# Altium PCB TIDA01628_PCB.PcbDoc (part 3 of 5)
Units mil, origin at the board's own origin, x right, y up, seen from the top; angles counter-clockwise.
Board outline 14212.6 x 5944.88 mil, 4 copper layers (Top Layer, GND, 5V, Bottom Layer), stack 60.8 mil thick; 304 components, 201 nets, 839 pads, 2143 vias.
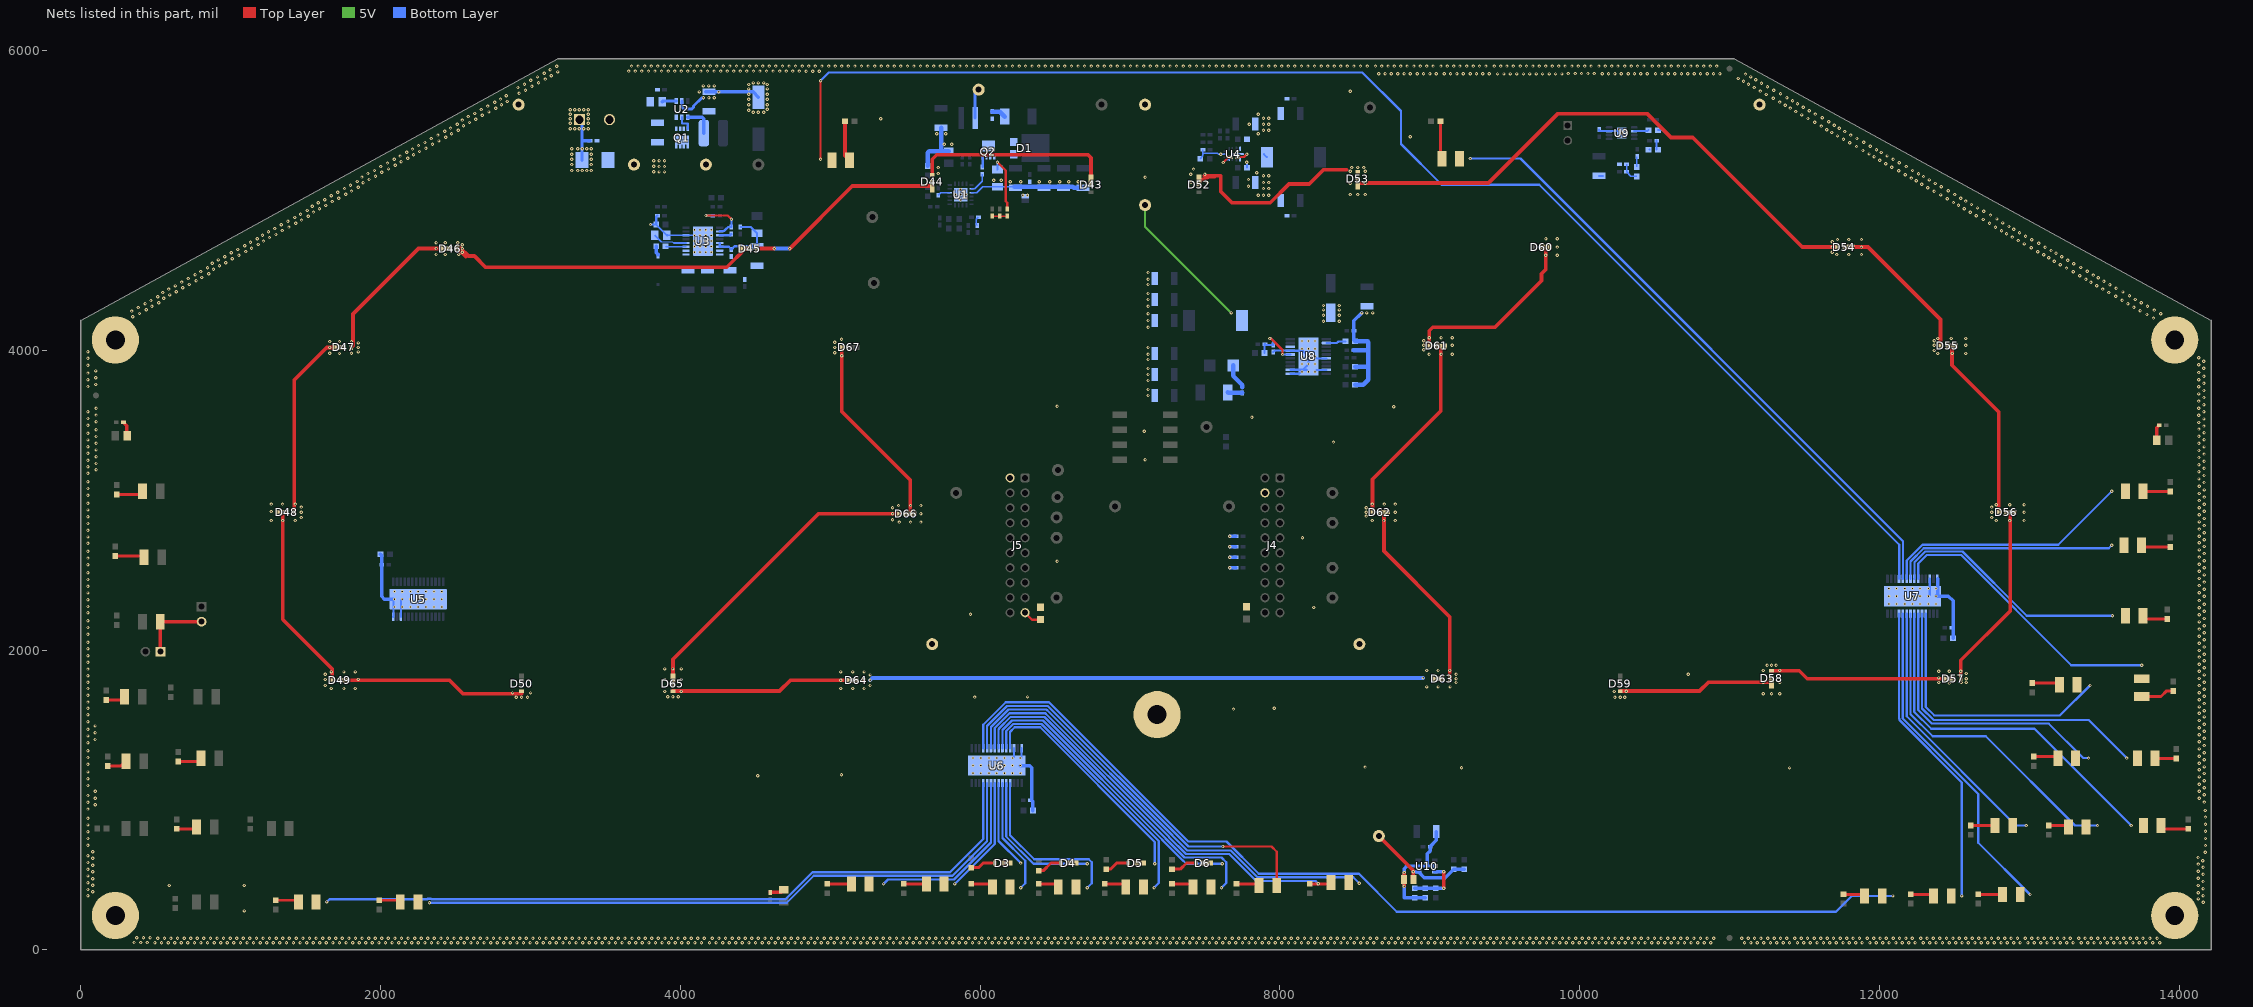
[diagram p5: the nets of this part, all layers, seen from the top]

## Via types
v1: diameter 22, hole 10, Top Layer to Bottom Layer, 1391 vias
v2: diameter 22, hole 10, Top Layer to Bottom Layer, tented both sides, 644 vias
v3: diameter 19.68, hole 7.87, Top Layer to Bottom Layer, tented both sides, 56 vias
v4: diameter 19.68, hole 7.87, Top Layer to Bottom Layer, 47 vias
v5: diameter 19.68, hole 7.87, Top Layer to Bottom Layer, tented top, 5 vias

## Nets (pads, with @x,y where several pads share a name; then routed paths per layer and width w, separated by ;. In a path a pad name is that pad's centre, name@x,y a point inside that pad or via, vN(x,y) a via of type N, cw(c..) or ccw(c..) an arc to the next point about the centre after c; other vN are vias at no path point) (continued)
GND: C2.2 C3.2 C4.2 C5.2 C6.2 C7.2 C8.2 C9.2 C10.2 C12.2 C16.2 C17.1 C20.2 C21.2 C23.2 C24.2 C25.2 C26.2 C29.2 C30.2 C31.2 C32.2 C33.1 C34.2 C35.2 C36.2 C37.2 C38.2 C40.2 C41.2 C42.2 C43.2 C44.2 C45.2 C46.2 C47.2 C48.2 C49.2 C50.2 C51.2 C52.2 C53.2 C55.2 C56.2 C57.2 C58.2 C59.2 C60.2 C62.2 C63.2 C64.2 C65.2 C66.2 C68.2 C69.2 C71.2 C72.2 C73.2 C74.2 C75.2 C76.2 D2.1 D68.2 D69.2 H1.1 H2.1 H3.1 H4.1 H5.1 J1.1 J4.4 J5.2 NTG1.2 Q3.1 R4.1 R17.1 R19.1 R23.1 R66.1 R68.1 R69.2 R78.1 R79.1 R80.1 R81.1 R82.1 TP7.1 TP8.1 TP9.1 TP10.1 TP11.1 U1.10 U1.17@5870,5040 U2.2 U3.6 U3.10 U3.15 U3.16 U3.17@4150,4730 U4.1 U4.6 U4.11 U5.26 U5.28 U5.29@2250,2340 U6.26 U6.28 U6.29@6110,1230 U7.26 U7.28 U7.29@12220,2360 U8.6 U8.9 U8.11 U8.12 U8.17 U8.21@8190,3960 U9.7 U9.9 U10.2 | length 8014
  Top Layer w15: v2(4170,4900) 4315,4900 v2(4340,4875)
  Top Layer w23: C42.2@283.62,3520 305.28,3498.35 305.28,3434.72 C43.2@310,3430 ; C44.2@4600,383.62 4673.62,383.62 C45.2@4690,400 ; v2(8828,424) 8828.5,424.5 v2(8828.5,516) ; C47.2@13850,3400 13850,3483.62 C46.2@13866.38,3500
  Bottom Layer w9: C40.2@7468.5,5280 C40.2@7486.38,5297.87 ; 7486.38,5310 7487.45,5311.07 ; v2@7603.93,5311.07 v2(7605,5310) U4.6@7634.88,5310
  Bottom Layer w10: U1.10@5941.85,5052.8 5977.8,5052.8 6017.91,5092.91 R4.1@6115.12,5092.91 6227.24,5092.91 C6.2@6235.12,5085.04 ; C40.2@7486.38,5297.87 7486.38,5310 R23.1@7486.38,5340 ; 7487.45,5311.07 7491.38,5315 7585,5315 7590,5310 v2(7605,5310)
  Bottom Layer w13: v2(3800,4840) C34.2@3838.5,4840 3840,4840 C33.1@3910,4770 ; C33.1@3911.61,4768.39 U3.6@4037.79,4768.39 4092.91,4768.39 v3(4093.9,4767.4) ; C30.2@7781.5,5220 v2@7781.5,5258.5 ; R66.1@7965.21,3998.39 U8.17@8069.92,3998.39 ; v3(8233.31,3857.64) 8246.1,3870.43 U8.9@8310.08,3870.43 ; v4(8233.31,3960) 8246.1,3947.2 U8.6@8310.08,3947.2 ; C68.2@10130,5165.04 C68.2@10155.04,5165.04 ; C69.2@10130,5473.62 10130,5465.15 10193.98,5465.15 U9.7@10196.34,5462.8 10251.46,5462.8 v4(10262.28,5473.62) ; C72.2@10466,5339.62 C72.2@10466.38,5340 ; C73.2@10521.5,5470 10550,5470 10567,5453
  Bottom Layer w15: U5.28@2083.66,2223.86 2085.02,2225.22 2085.02,2340 v3(2092.52,2340) ; U5.26@2134.84,2223.86 2134.84,2331.14 v3(2143.7,2340) ; C34.2@3838.5,4840 3838.5,4892.13 R17.1@3846.38,4900 ; C33.1@3910,4770 C33.1@3911.61,4768.39 ; v2(4170,4900) R19.1@4216.38,4900 ; U3.10@4262.2,4793.98 4264.55,4796.32 4291.04,4796.32 4301.2,4806.48 4301.2,4806.7 4318.12,4823.62 C41.2@4340,4823.62 v2(4340,4875) ; v3(6216.3,1281.18) 6225.16,1290.04 U6.26@6225.16,1346.14 ; v3(6267.48,1281.18) 6274.98,1281.18 6274.98,1344.78 U6.28@6276.34,1346.14 ; R66.1@7956,3989.18 R66.1@7965.21,3998.39 ; U8.11@8069.92,3844.84 8127.2,3844.84 U8.21@8152.8,3870.43 ; U8.12@8069.92,3870.43 U8.21@8152.8,3870.43 ; U8.17@8069.92,3998.39 8151.61,3998.39 v4(8190,3960) v4(8190,3908.82) 8190,3907.64 U8.21@8152.8,3870.43 ; v3(8190,3857.64) 8177.2,3870.43 U8.21@8152.8,3870.43 ; v3(12326.3,2360) 12335.16,2368.86 U7.26@12335.16,2476.14
  Bottom Layer w20: U2.2@4010,5664.13 4010,5621.83 4019.83,5612 4076.9,5612 4087.13,5622.23 4087.13,5630.62 4141.5,5685 v2(4153.69,5685)
  Bottom Layer w23: C49.2@1998.5,2640 2006.38,2632.13 C48.2@2006.38,2570 2006.38,2358.62 2025,2340 U5.29@2085.02,2340 ; J1.1@3326.55,5540 3342.99,5523.55 3342.99,5396.78 ; D2.1@3342.99,5270 3342.99,5396.78 ; C10.2@3396.38,5400 3346.21,5400 3342.99,5396.78 ; C2.2@4169.96,5724.96 C2.2@4190,5724.96 4484.8,5724.96 C8.2@4520,5689.76 ; v3(6267.48,1230) 6330,1230 6343.62,1216.38 6343.62,1000 6351.5,992.13 C53.2@6351.5,930 ; v2(7665,2550) R82.1@7706.38,2550 ; v2(7665,2620) R81.1@7706.38,2620 ; v2(7665,2690) R80.1@7706.38,2690 ; v2(7665,2760) R79.1@7706.38,2760 ; C66.2@8501.18,4060 8493.62,4067.56 C62.2@8493.62,4130 8493.62,4198.62 v2(8545,4250) ; R78.1@8968.7,348.5 C74.2@8898.7,348.5 8828.5,348.5 v2(8828.5,516) 8828.5,542.5 8846,560 U10.2@9032.83,560 ; 8984,562 8984,642 9002.32,660.32 C76.2@9002.32,690 9043.66,731.34 C75.2@9043.66,790 ; U7.28@12388.98,2476.14 12388.98,2371.5 v3(12377.48,2360) 12460,2360 12491.5,2328.5 C51.2@12491.5,2080
  Bottom Layer w30: C17.1@5650,5231.5 5650,5320 5660,5330 5740,5330 ; C12.2@5740,5485.04 5740,5330 ; C16.2@5790,5330 5740,5330 ; C6.2@6227.24,5092.91 6617.24,5092.91 6625.12,5085.04 C5.2@6683.78,5085.04 ; R68.1@8493.62,4000 8585,4000 8590,3995 ; C66.2@8501.18,4060 8585,4060 8590,4055 8590,3995 ; R69.2@8501.5,3770 8555,3770 8590,3805 8590,3890 ; C65.2@8501.5,3890 8590,3890 ; 8590,3890 8590,3995
  other v1: 494.04,47.45 537.89,47.45 581.74,47.45 625.59,47.45 669.44,47.45 713.29,47.45 757.14,47.45 800.99,47.45 844.84,47.45 888.69,47.45 932.54,47.45 976.39,47.45 1020.24,47.45 1064.09,47.45 1107.94,47.45 1151.79,47.45 1195.64,47.45 1239.49,47.45 1283.34,47.45 1327.19,47.45 1371.04,47.45 1418.04,47.45 1461.89,47.45 1505.74,47.45 1549.59,47.45 1593.44,47.45 1637.29,47.45 1681.14,47.45 1724.99,47.45 1768.84,47.45 1812.69,47.45 1856.54,47.45 1900.39,47.45 1944.24,47.45 1988.09,47.45 2031.94,47.45 2075.79,47.45 2119.64,47.45 2163.49,47.45 2207.34,47.45 2251.19,47.45 2295.04,47.45 2338.89,47.45 2382.74,47.45 2426.59,47.45 2470.44,47.45 2514.29,47.45 2558.14,47.45 2601.99,47.45 2645.84,47.45 2689.69,47.45 2733.54,47.45 2777.39,47.45 2821.24,47.45 2865.09,47.45 2908.94,47.45 2952.79,47.45 2996.64,47.45 3040.49,47.45 3084.34,47.45 3128.19,47.45 3172.04,47.45 3215.89,47.45 3259.74,47.45 3303.59,47.45 3347.44,47.45 3391.29,47.45 3435.14,47.45 3478.99,47.45 3522.84,47.45 3566.69,47.45 3610.54,47.45 3658.04,47.45 3701.89,47.45 3745.74,47.45 3789.59,47.45 3833.44,47.45 3877.29,47.45 3921.14,47.45 3964.99,47.45 4008.84,47.45 4052.69,47.45 4096.54,47.45 4140.39,47.45 4194.04,47.45 4237.89,47.45 4281.74,47.45 4325.59,47.45 4369.44,47.45 4413.29,47.45 4457.14,47.45 4500.99,47.45 4544.84,47.45 4588.69,47.45 4632.54,47.45 4676.39,47.45 4720.24,47.45 4764.09,47.45 4807.94,47.45 4851.79,47.45 4895.64,47.45 4939.49,47.45 4983.34,47.45 5027.19,47.45 5071.04,47.45 5114.89,47.45 5158.74,47.45 5202.59,47.45 5246.44,47.45 5290.29,47.45 5334.14,47.45 5377.99,47.45 5421.84,47.45 5465.69,47.45 5509.54,47.45 5553.39,47.45 5597.24,47.45 5641.09,47.45 5684.94,47.45 5728.79,47.45 5772.64,47.45 5816.49,47.45 5860.34,47.45 5904.19,47.45 5948.04,47.45 5991.89,47.45 6035.74,47.45 6079.59,47.45 6123.44,47.45 6167.29,47.45 6211.14,47.45 6254.99,47.45 6298.84,47.45 6342.69,47.45 6386.54,47.45 6434.04,47.45 6477.89,47.45 6521.74,47.45 6565.59,47.45 6609.44,47.45 6653.29,47.45 6697.14,47.45 6740.99,47.45 6784.84,47.45 6828.69,47.45 6872.54,47.45 6916.39,47.45 6960.24,47.45 7004.09,47.45 7047.94,47.45 7091.79,47.45 7135.64,47.45 7179.49,47.45 7223.34,47.45 7267.19,47.45 7311.04,47.45 7354.89,47.45 7398.74,47.45 7442.59,47.45 7486.44,47.45 7530.29,47.45 7574.14,47.45 7617.99,47.45 7661.84,47.45 7705.69,47.45 7749.54,47.45 7793.39,47.45 7837.24,47.45 7881.09,47.45 7924.94,47.45 7968.79,47.45 8012.64,47.45 8056.49,47.45 8100.34,47.45 8144.19,47.45 8188.04,47.45 8231.89,47.45 8275.74,47.45 8319.59,47.45 8363.44,47.45 8407.29,47.45 8451.14,47.45 8494.99,47.45 8538.84,47.45 8582.69,47.45 8626.54,47.45 8682.04,47.45 8725.89,47.45 8769.74,47.45 8813.59,47.45 8857.44,47.45 8901.29,47.45 8945.14,47.45 8988.99,47.45 9032.84,47.45 9076.69,47.45 9120.54,47.45 9164.39,47.45 9208.24,47.45 9252.09,47.45 9295.94,47.45 9339.79,47.45 9383.64,47.45 9427.49,47.45 9471.34,47.45 9515.19,47.45 9559.04,47.45 9602.89,47.45 9646.74,47.45 9690.59,47.45 9734.44,47.45 9778.29,47.45 9822.14,47.45 9865.99,47.45 9909.84,47.45 9953.69,47.45 9997.54,47.45 10041.39,47.45 10085.24,47.45 10129.09,47.45 10172.94,47.45 10216.79,47.45 10260.64,47.45 10304.49,47.45 10348.34,47.45 10392.19,47.45 10436.04,47.45 10479.89,47.45 10523.74,47.45 10567.59,47.45 10611.44,47.45 10655.29,47.45 10699.14,47.45 10742.99,47.45 10786.84,47.45 10830.69,47.45 10874.54,47.45 13823,47 13870,47 11100,47.92 11142.44,47.92 11184.87,47.92 11227.31,47.92 11273,47.92 11315.44,47.92 11357.87,47.92 11400.31,47.92 11453,47.92 11495.44,47.92 11537.87,47.92 11584,47.92 11626.44,47.92 11668.87,47.92 11711.31,47.92 11757,47.92 11799.44,47.92 11841.87,47.92 11884.31,47.92 11937,47.92 11979.44,47.92 12021.87,47.92 12064.31,47.92 12110,47.92 12152.44,47.92 12194.87,47.92 12237.31,47.92 12293,47.92 12335.44,47.92 12377.87,47.92 12420.31,47.92 12466,47.92 12508.44,47.92 12550.87,47.92 12593.31,47.92 12637.44,47.92 12679.87,47.92 12722.31,47.92 12765.5,47.92 12811.19,47.92 12853.63,47.92 12896.06,47.92 12938.5,47.92 12991.19,47.92 13033.63,47.92 13076.06,47.92 13118.5,47.92 13164.19,47.92 13206.63,47.92 13249.06,47.92 13291.5,47.92 13347.19,47.92 13389.63,47.92 13432.06,47.92 13474.5,47.92 13520.19,47.92 13562.63,47.92 13605.06,47.92 13647.5,47.92 13691.63,47.92 13734.06,47.92 13776.5,47.92 354.22,49.52 398.07,49.52 441.92,49.52 13805,78 13852,78 513.13,78.92 556.98,78.92 600.83,78.92 644.68,78.92 688.53,78.92 732.38,78.92 776.23,78.92 820.08,78.92 863.93,78.92 907.78,78.92 951.63,78.92 995.48,78.92 1039.33,78.92 1083.18,78.92 1127.03,78.92 1170.88,78.92 1214.73,78.92 1258.58,78.92 1302.43,78.92 1346.28,78.92 1390.13,78.92 1437.13,78.92 1480.98,78.92 1524.83,78.92 1568.68,78.92 1612.53,78.92 1656.38,78.92 1700.23,78.92 1744.08,78.92 1787.93,78.92 1831.78,78.92 1875.63,78.92 1919.48,78.92 1963.33,78.92 2007.18,78.92 2051.03,78.92 2094.88,78.92 2138.73,78.92 2182.58,78.92 2226.43,78.92 2270.28,78.92 2314.13,78.92 2357.98,78.92 2401.83,78.92 2445.68,78.92 2489.53,78.92 2533.38,78.92 2577.23,78.92 2621.08,78.92 2664.93,78.92 2708.78,78.92 2752.63,78.92 2796.48,78.92 2840.33,78.92 2884.18,78.92 2928.03,78.92 2971.88,78.92 3015.73,78.92 3059.58,78.92 3103.43,78.92 3147.28,78.92 3191.13,78.92 3234.98,78.92 3278.83,78.92 3322.68,78.92 3366.53,78.92 3410.38,78.92 3454.23,78.92 3498.08,78.92 3541.93,78.92 3585.78,78.92 3629.63,78.92 3677.13,78.92 3720.98,78.92 3764.83,78.92 3808.68,78.92 3852.53,78.92 3896.38,78.92 3940.23,78.92 3984.08,78.92 4027.93,78.92 4071.78,78.92 4115.63,78.92 4159.48,78.92 4213.13,78.92 4256.98,78.92 4300.83,78.92 4344.68,78.92 4388.53,78.92 4432.38,78.92 4476.23,78.92 4520.08,78.92 4563.93,78.92 4607.78,78.92 4651.63,78.92 4695.48,78.92 4739.33,78.92 4783.18,78.92 4827.03,78.92 4870.88,78.92 4914.73,78.92 4958.58,78.92 5002.43,78.92 5046.28,78.92 5090.13,78.92 5133.98,78.92 5177.83,78.92 5221.68,78.92 5265.53,78.92 5309.38,78.92 5353.23,78.92 5397.08,78.92 5440.93,78.92 5484.78,78.92 5528.63,78.92 5572.48,78.92 5616.33,78.92 5660.18,78.92 5704.03,78.92 5747.88,78.92 5791.73,78.92 5835.58,78.92 5879.43,78.92 5923.28,78.92 5967.13,78.92 6010.98,78.92 6054.83,78.92 6098.68,78.92 6142.53,78.92 6186.38,78.92 6230.23,78.92 6274.08,78.92 6317.93,78.92 6361.78,78.92 6405.63,78.92 6453.13,78.92 6496.98,78.92 6540.83,78.92 6584.68,78.92 6628.53,78.92 6672.38,78.92 6716.23,78.92 6760.08,78.92 6803.93,78.92 6847.78,78.92 6891.63,78.92 6935.48,78.92 6979.33,78.92 7023.18,78.92 7067.03,78.92 7110.88,78.92 7154.73,78.92 7198.58,78.92 7242.43,78.92 7286.28,78.92 7330.13,78.92 7373.98,78.92 7417.83,78.92 7461.68,78.92 7505.53,78.92 7549.38,78.92 7593.23,78.92 7637.08,78.92 7680.93,78.92 7724.78,78.92 7768.63,78.92 7812.48,78.92 7856.33,78.92 7900.18,78.92 7944.03,78.92 7987.88,78.92 8031.73,78.92 8075.58,78.92 8119.43,78.92 8163.28,78.92 8207.13,78.92 8250.98,78.92 8294.83,78.92 8338.68,78.92 8382.53,78.92 8426.38,78.92 8470.23,78.92 8514.08,78.92 8557.93,78.92 8601.78,78.92 8645.63,78.92 8701.13,78.92 8744.98,78.92 8788.83,78.92 8832.68,78.92 8876.53,78.92 8920.38,78.92 8964.23,78.92 9008.08,78.92 9051.93,78.92 9095.78,78.92 9139.63,78.92 9183.48,78.92 9227.33,78.92 9271.18,78.92 9315.03,78.92 9358.88,78.92 9402.73,78.92 9446.58,78.92 9490.43,78.92 9534.28,78.92 9578.13,78.92 9621.98,78.92 9665.83,78.92 9709.68,78.92 9753.53,78.92 9797.38,78.92 9841.23,78.92 9885.08,78.92 9928.93,78.92 9972.78,78.92 10016.63,78.92 10060.48,78.92 10104.33,78.92 10148.18,78.92 10192.03,78.92 10235.88,78.92 10279.73,78.92 10323.58,78.92 10367.43,78.92 10411.28,78.92 10455.13,78.92 10498.98,78.92 10542.83,78.92 10586.68,78.92 10630.53,78.92 10674.38,78.92 10718.23,78.92 10762.08,78.92 10805.93,78.92 10849.78,78.92 10893.63,78.92 11082,78.92 11124.44,78.92 11166.87,78.92 11209.31,78.92 11255,78.92 11297.44,78.92 11339.87,78.92 11382.31,78.92 11435,78.92 11477.44,78.92 11519.87,78.92 11566,78.92 11608.44,78.92 11650.87,78.92 11693.31,78.92 11739,78.92 11781.44,78.92 11823.87,78.92 11866.31,78.92 11919,78.92 11961.44,78.92 12003.87,78.92 12046.31,78.92 12092,78.92 12134.44,78.92 12176.87,78.92 12219.31,78.92 12275,78.92 12317.44,78.92 12359.87,78.92 12402.31,78.92 12448,78.92 12490.44,78.92 12532.87,78.92 12575.31,78.92 12619.44,78.92 12661.87,78.92 12704.31,78.92 12747.5,78.92 12793.19,78.92 12835.63,78.92 12878.06,78.92 12920.5,78.92 12973.19,78.92 13015.63,78.92 13058.06,78.92 13100.5,78.92 13146.19,78.92 13188.63,78.92 13231.06,78.92 13273.5,78.92 13329.19,78.92 13371.63,78.92 13414.06,78.92 13456.5,78.92 13502.19,78.92 13544.63,78.92 13587.06,78.92 13629.5,78.92 13673.63,78.92 13716.06,78.92 13758.5,78.92 373.3,81 417.15,81 461,81 14160,319 14128,340 47,361 14159,361.43 14127,382.43 79,388 47,403.87 14159,409 79,430.87 14127,430 47,448.86 14159,456.57 79,475.86 14127,477.57 47,493.85 14159,504.14 79,520.85 14127,525.14 47,538.85 14159,551.71 79,565.85 14127,572.71 47,583.84 14158,595.71 79,610.84 14126,616.71 47,628.83 14174,651 79,655.83 14175,696.43 47,698.86 47,743.85 14175,744 47,788.85 14175,791.57 47,833.84 14175,839.14 47,878.83 14175,886.71 14174,930.71 47,940.29 96,967.85 47,985.29 14167.93,986.97 14134,1011.29 96,1012.84 47,1030.28 14167.93,1034.54 96,1057.83 14134,1058.86 14167.93,1082.11 47,1097.45 14134,1106.43 14167.93,1129.68 47,1142.44 14134,1154 14167.93,1177.25 47,1187.43 14134,1201.57 14166.93,1221.26 47,1238.45 14133,1245.57 14166.93,1268.83 47,1283.44 14133,1293.14 14166.93,1316.4 47,1328.43 14133,1340.71 14166.93,1363.97 47,1382.45 14133,1388.29 93.88,1404.45 14166.93,1411.54 47,1427.44 14133,1435.86 93.88,1449.44 14166.93,1459.11 47,1472.43 14133,1483.43 93.88,1494.43 14166.93,1506.68 47,1523.45 14133,1531 14166.93,1554.25 47,1568.44 14133,1578.57 14167.93,1596.68 47,1613.43 14134,1621 14167.93,1644.25 47,1653.77 14134,1668.57 14167.93,1691.83 47,1698.77 14134,1716.14 14167.93,1739.4 47,1743.76 14134,1763.71 47,1786 14167.93,1786.97 14134,1811.29 47,1828.87 14167.93,1834.54 14134,1858.86 47,1873.86 14167.93,1882.11 14134,1906.43 47,1918.85 14167.93,1929.68 14134,1954 47,1963.85 14166.93,1973.68 14133,1998 47,2008.84 14166.93,2021.25 14133,2045.57 47,2053.83 14166.93,2068.83 14133,2093.14 47,2106.85 14166.93,2116.4 14133,2140.71 47,2151.84 14166.93,2163.97 14133,2188.29 47,2196.83 14166.93,2211.54 14133,2235.86 47,2249 14166.93,2259.11 14133,2283.43 47,2291.87 14166.93,2306.68 14133,2331 47,2336.86 14167.93,2359.26 47,2381.85 14134,2383.57 14167.93,2406.83 47,2426.85 14134,2431.14 14167.93,2454.4 47,2471.84 14134,2478.71 14167.93,2501.97 47,2516.83 14134,2526.29 14167.93,2549.54 47,2569.85 14134,2573.86 14167.93,2597.11 47,2614.84 14134,2621.43 14167.93,2644.68 47,2659.83 14134,2669 14167.93,2692.25 47,2713 14134,2716.57 14166.93,2736.26 47,2755.87 14133,2760.57 14166.93,2783.83 47,2800.86 14133,2808.14 14166.93,2831.4 47,2845.85 14133,2855.71 14166.93,2878.97 47,2890.85 14133,2903.29 14166.93,2926.54 47,2935.84 14133,2950.86 14166.93,2974.11 47,2980.83 14133,2998.43 14166.93,3021.68 47,3033.85 14133,3046 14166.93,3069.25 47,3078.84 14133,3093.57 14165.93,3118.26 47,3123.83 14132,3142.57 14165.93,3165.83 47,3180.16 14132,3190.14 101,3203 14165.93,3213.4 47,3223.03 14132,3237.71 101,3245.87 14165.93,3260.97 47,3268.02 14132,3285.29 101,3290.86 14165.93,3308.54 47,3313.01 14132,3332.86 101,3335.85 14165.93,3356.11 47,3358.01 101,3380.85 14132,3380.43 47,3403 14165.93,3403.68 101,3425.84 14132,3428 47,3447.99 14165.93,3451.25 101,3470.83 14132,3475.57 14164.93,3495.26 47,3501.01 14131,3519.57 101,3523.85 14164.93,3542.83 47,3546 14131,3567.14 101,3568.84 14164.93,3590.4 47,3590.99 101,3613.83 14131,3614.71 14164.93,3637.97 14131,3662.29 14164.93,3685.54 14131,3709.86 14164.93,3733.11 14131,3757.43 47,3759.01 99,3772.85 14164.93,3780.68 47,3804 14131,3805 99,3817.84 14164.93,3828.25 47,3848.99 14131,3852.57 99,3862.83 14163.93,3880.68 47,3902.01 14130,3905 14163.93,3927.68 47,3947 14130,3952 47,3991.99 13828,4216 346,4224 13785,4240.31 13877,4245 390,4247 339,4263 13739,4265.31 13834,4269.31 435,4272 383,4286 13698,4288.31 474,4294 13788,4294.31 428,4311 13658,4311.31 13747,4317.31 519,4319 467,4333 13619,4335.31 13707,4340.31 553,4347.31 512,4358 13576,4361.31 13668,4364.31 593,4370.31 546,4386.31 13530,4386.31 13625,4390.31 636,4391.31 586,4409.31 13489,4409.31 13579,4415.31 679,4417.31 629,4430.31 13449,4432.31 13538,4438.31 723,4440.31 13411,4455.31 672,4456.31 13498,4461.31 768,4465.31 13378,4474.31 716,4479.31 13460,4484.31 807,4487.31 13337.06,4498.57 13427,4503.31 761,4504.31 852,4512.31 13294.06,4524.57 800,4526.31 13386.06,4527.57 884,4542 13248.06,4549.57 845,4551.31 13343.06,4553.57 924,4565 13207.06,4572.57 13297.06,4578.57 877,4581 967,4586 13167.06,4595.57 13256.06,4601.57 917,4604 1010,4612 13129.06,4618.57 13216.06,4624.57 960,4625 1054,4635 13096.06,4637.57 13178.06,4647.57 1003,4651 13056,4659.31 1099,4660 13145.06,4666.57 1047,4674 1138,4682 13013,4685.31 13105,4688.31 1092,4699 1183,4707 12967,4710.31 13062,4714.31 1131,4721 1218,4730 12926,4733.31 13016,4739.31 1176,4746 1258,4753 12886,4756.31 12975,4762.31 1211,4769 1301,4774 12848,4779.31 12935,4785.31 1251,4792 12815,4798.31 1344,4800 12897,4808.31 1294,4813 12774,4821.62 1388,4823 12864,4827.31 1337,4839 1433,4848 12735,4848 12823,4850.62 1381,4862 1472,4870 12692,4874 12784,4877 1426,4887 1517,4895 12646,4899 12741,4903 1465,4909 12605,4922 1551,4923.31 12695,4928 1510,4934 12565,4945 1591,4946.31 12654,4951 1544,4962.31 1634,4967.31 12527,4968 12614,4974 1584,4985.31 12494,4987 1677,4993.31 12576,4997 1627,5006.31 12453.06,5011.26 1721,5016.31 12543,5016 1670,5032.31 12410.06,5037.26 12502.06,5040.26 1766,5041.31 1714,5055.31 12364.06,5062.26 1805,5063.31 12459.06,5066.26 1759,5080.31 12323.06,5085.26 1850,5088.31 12413.06,5091.26 1798,5102.31 12283.06,5108.26 12372.06,5114.26 1882,5118 1843,5127.31 12245.06,5131.26 12332.06,5137.26 1922,5141 12212.06,5150.26 1875,5157 12294.06,5160.26 1965,5162 12172,5172 12261.06,5179.26 1915,5180 2008,5188 3857.12,5190.95 3893.43,5190.95 3821,5192.38 12129,5198 1958,5201 12221,5201 2052,5211 12083,5223 2001,5227 3857.12,5227.26 3893.43,5227.26 12178,5227 3821,5228.69 2097,5236 12042,5246 2045,5250 12132,5252 2136,5258 3821,5265 3857.31,5264.99 3893.62,5264.99 12002,5269 2090,5275 12091,5275 2181,5283 11964,5292 2129,5297 12051,5298 2219,5305 11931,5311 12013,5321 2174,5322 2259,5328 11890,5334.31 11980,5340 2212,5344 2302,5349 11847,5360.31 11939,5363.31 2252,5367 2345,5375 11801,5385.31 2295,5388 11896,5389.31 2389,5398 11760,5408.31 2338,5414 11850,5414.31 2434,5423 11720,5431.31 2382,5437 11809,5437.31 2473,5445 11682,5454.31 11769,5460.31 2427,5462 2518,5470 11649,5473.31 11731,5483.31 2466,5484 11612,5497 2552,5498.31 11698,5502.31 2511,5509 2592,5521.31 11569,5523 11661,5526 2545,5537.31 2635,5542.31 11523,5548 11618,5552 2585,5560.31 2678,5568.31 11482,5571 11572,5577 2628,5581.31 2722,5591.31 11442,5594 11531,5600 2671,5607.31 2767,5616.31 11404,5617 11491,5623 2715,5630.31 11371,5636 2806,5638.31 11453,5646 2760,5655.31 11334,5657 2844,5661 11420,5665 2799,5677.31 11291,5683 11383,5686 2837,5700 11245,5708 11340,5712 2923,5716 11204,5731 2966,5737 11294,5737 11164,5754 2916,5755 11253,5760 3009,5763 2959,5776 11126,5777 11213,5783 3053,5786 11093,5796 3002,5802 11175,5806 3098,5811 11057,5815 3046,5825 11142,5825 3137,5833 11106,5844 9452,5845 9494.44,5845 9536.87,5845 9579.31,5845 9625,5845 9667.44,5845 9709.87,5845 9752.31,5845 9796.44,5845 9838.87,5845 9881.31,5845 10506.19,5845.23 10548.63,5845.23 10591.06,5845.23 10633.5,5845.23 10679.19,5845.23 10721.63,5845.23 10764.06,5845.23 10806.5,5845.23 10850.63,5845.23 10893.06,5845.23 10935.5,5845.23 9096,5846 9138.44,5846 9180.87,5846 9223.31,5846 9269,5846 9311.44,5846 9353.87,5846 9396.31,5846 10150.19,5846.23 10192.63,5846.23 10235.06,5846.23 10277.5,5846.23 10323.19,5846.23 10365.63,5846.23 10408.06,5846.23 10450.5,5846.23 8659,5847 8701.44,5847 8743,5847 8785.44,5847 8827.87,5847 8870.31,5847 8916,5847 8958.44,5847 9000.87,5847 9043.31,5847 9924.5,5847.23 9970.19,5847.23 10012.63,5847.23 10055.06,5847.23 10097.5,5847.23 3091,5850 3182,5858 4838.06,5862.45 4881.84,5862.45 4925.63,5862.45 3655.03,5864 3698.82,5864 3742.6,5864 3786.38,5864 3830.16,5864 3873.94,5864 3917.72,5864 3961.5,5864 4005.28,5864 4049.06,5864 4092.85,5864 4136.63,5864 4180.41,5864 4224.19,5864 4267.97,5864 4311.75,5864 4355.53,5864 4399.31,5864 4443.09,5864 4486.88,5864 4530.66,5864 4574.44,5864 4618.22,5864 4662,5864 4705.78,5864 4749.56,5864 4793.34,5864 3130,5872 3175,5897 3673.56,5897.55 3717.34,5897.55 3761.13,5897.55 3804.91,5897.55 3848.69,5897.55 3892.47,5897.55 3936.25,5897.55 3980.03,5897.55 4023.81,5897.55 4067.59,5897.55 4111.37,5897.55 4155.16,5897.55 4198.94,5897.55 4242.72,5897.55 4286.5,5897.55 4330.28,5897.55 4374.06,5897.55 4417.84,5897.55 4461.62,5897.55 4505.4,5897.55 4549.19,5897.55 4592.97,5897.55 4636.75,5897.55 4680.53,5897.55 4724.31,5897.55 4768.09,5897.55 4811.87,5897.55 4856.59,5897.55 4900.37,5897.55 4944.15,5897.55 4989.03,5897.55 5032.82,5897.55 5076.6,5897.55 5120.38,5897.55 5164.16,5897.55 5207.94,5897.55 5251.72,5897.55 5295.5,5897.55 5339.28,5897.55 5383.06,5897.55 5426.85,5897.55 5470.63,5897.55 5514.41,5897.55 5558.19,5897.55 5601.97,5897.55 5645.75,5897.55 5689.53,5897.55 5733.31,5897.55 5777.09,5897.55 5820.88,5897.55 5864.66,5897.55 5908.44,5897.55 5952.22,5897.55 5996,5897.55 6039.78,5897.55 6083.56,5897.55 6127.34,5897.55 6172.06,5897.55 6215.84,5897.55 6259.63,5897.55 6302.47,5897.55 6346.25,5897.55 6390.03,5897.55 6433.81,5897.55 6477.59,5897.55 6521.37,5897.55 6565.16,5897.55 6608.94,5897.55 6652.72,5897.55 6696.5,5897.55 6740.28,5897.55 6784.06,5897.55 6827.84,5897.55 6871.62,5897.55 6915.4,5897.55 6959.19,5897.55 7002.97,5897.55 7046.75,5897.55 7090.53,5897.55 7134.31,5897.55 7178.09,5897.55 7221.87,5897.55 7266.59,5897.55 7310.37,5897.55 7354.15,5897.55 7399.03,5897.55 7442.82,5897.55 7486.6,5897.55 7530.38,5897.55 7574.16,5897.55 7617.94,5897.55 7661.72,5897.55 7705.5,5897.55 7749.28,5897.55 7793.06,5897.55 7836.85,5897.55 7880.63,5897.55 7924.41,5897.55 7968.19,5897.55 8011.97,5897.55 8055.75,5897.55 8099.53,5897.55 8143.31,5897.55 8187.09,5897.55 8230.88,5897.55 8274.66,5897.55 8318.44,5897.55 8362.22,5897.55 8406,5897.55 8449.78,5897.55 8493.56,5897.55 8537.34,5897.55 8582.06,5897.55 8637,5897.55 8679.44,5897.55 8721,5897.55 8763.44,5897.55 8805.87,5897.55 8848.31,5897.55 8894,5897.55 8936.44,5897.55 8978.87,5897.55 9021.31,5897.55 9074,5897.55 9116.44,5897.55 9158.87,5897.55 9201.31,5897.55 9247,5897.55 9289.44,5897.55 9331.87,5897.55 9374.31,5897.55 9430,5897.55 9472.44,5897.55 9514.87,5897.55 9557.31,5897.55 9603,5897.55 9645.44,5897.55 9687.87,5897.55 9730.31,5897.55 9774.44,5897.55 9816.87,5897.55 9859.31,5897.55 9902.5,5897.55 9948.19,5897.55 9990.63,5897.55 10033.06,5897.55 10075.5,5897.55 10128.19,5897.55 10170.63,5897.55 10213.06,5897.55 10255.5,5897.55 10301.19,5897.55 10343.63,5897.55 10386.06,5897.55 10428.5,5897.55 10484.19,5897.55 10526.63,5897.55 10569.06,5897.55 10611.5,5897.55 10657.19,5897.55 10699.63,5897.55 10742.06,5897.55 10784.5,5897.55 10828.63,5897.55 10871.06,5897.55 10913.5,5897.55
  other v2: 1090,260 590,430 1090,430 4515,1163 5074,1168 11400,1214 9212,1215 8568,1220 7690,1607 7963,1613 5963,1687 6316,1688 10725,1840 5935,2240 8225,2285 6513,2593 8150,2750 7100,3270 8357,3389 7095,3460 7813,3555 8759,3625 6513,3628 7120,3700 7120,3740 7120,3800 7120,3840 7120,3880 7120,3940 7120,3975 7120,4020 7120,4155 8290,4195 8395,4195 7120,4200 8290,4235 8395,4235 7120,4245 8580,4250 8620,4250 8290,4270 8395,4270 7120,4295 8290,4300 8395,4300 7120,4340 7120,4380 7120,4440 7120,4475 7120,4520 6285,5035 6315,5035 7855,5035 7890,5035 7925,5035 7890,5080 7925,5080 7790,5095 7890,5120 7925,5120 6200,5125 6270,5125 6395,5125 6465,5125 6530,5125 6590,5125 6655,5125 6090,5135 6140,5135 7790,5140 7100,5155 7890,5165 7925,5165 7845,5185 3275,5200 3315,5200 3345,5200 3375,5200.5 3405,5200 3275,5240 3405,5240 7778.69,5255 3275,5275 3405,5275 3275,5310 3405,5310 3275,5345 3315,5345 3345,5345 3375,5345 3405,5345 5760,5375 5810,5375 8870,5425 5709.41,5445 5770.59,5445 7855,5445 7890,5470 7925,5470 3265,5480 3295,5480 3325,5480 3355,5480 3385,5480 7795,5510 7890,5510 7925,5510 3265,5515 3385,5515 3265,5545 3385,5545 5336,5546 7890,5550 7925,5550 3265,5575 3385,5575 7855,5575 4485,5590 4520,5590 4556.31,5590 4455,5602.38 3265,5605 3295,5605 3325,5605 3355,5605 3385,5605 4580,5610 4455,5638.69 4580,5638.69 4455,5675 4580,5675 4190,5685 4226.22,5685.69 4455,5710 4580,5710 4125,5725 4255,5724.96 8470,5730 4455,5745 4580,5745 4152.38,5765 4188.69,5765 4225,5765 4455,5775 4580,5775 4485,5785 4520,5785 4555,5785
  other v3: 5952.52,1178.82 6003.7,1178.82 6216.3,1178.82 6267.48,1178.82 5952.52,1230 6003.7,1230 6216.3,1230 5952.52,1281.18 6003.7,1281.18 2092.52,2288.82 2143.7,2288.82 2356.3,2288.82 2407.48,2288.82 12062.52,2308.82 12113.7,2308.82 12326.3,2308.82 12377.48,2308.82 2356.3,2340 2407.48,2340 12062.52,2360 12113.7,2360 2092.52,2391.18 2143.7,2391.18 2356.3,2391.18 2407.48,2391.18 12062.52,2411.18 12113.7,2411.18 12326.3,2411.18 12377.48,2411.18 8146.69,3857.64 8146.69,4062.36 8190,4062.36 8233.31,4062.36 4093.9,4655.2 4131.3,4655.2 4168.7,4655.2 4206.1,4655.2 4093.9,4692.6 4206.1,4692.6 4093.9,4730 4206.1,4730 4206.1,4767.4 4093.9,4804.81 4131.3,4804.81 4168.7,4804.81 4206.1,4804.81
  other v4: 6058.82,1178.82 6110,1178.82 6161.18,1178.82 6058.82,1230 6110,1230 6161.18,1230 6058.82,1281.18 6110,1281.18 6161.18,1281.18 2198.82,2288.82 2250,2288.82 2301.18,2288.82 12168.82,2308.82 12220,2308.82 12271.18,2308.82 2198.82,2340 2250,2340 2301.18,2340 12168.82,2360 12220,2360 12271.18,2360 2198.82,2391.18 2250,2391.18 2301.18,2391.18 12168.82,2411.18 12220,2411.18 12271.18,2411.18 8146.69,3908.82 8233.31,3908.82 8146.69,3960 8146.69,4011.18 8190,4011.18 8233.31,4011.18 4131.3,4692.6 4168.7,4692.6 4131.3,4730 4168.7,4730 4131.3,4767.4 4168.7,4767.4 10262.28,5426.38 10297.72,5426.38 10280,5450 10297.72,5473.62
  other v5: 5870,5004.57 5834.57,5040 5870,5040 5905.43,5040 5870,5075.43
KL30_Power: C9.1 C10.1 C11.1 D2.2 J1.2 Q1.1 Q1.2 Q1.3 R8.1 TP3.1 U2.6
L0: D24.2 U6.11 | length 4931.2
  Bottom Layer w15: v2(1640,320) 1657.87,337.87 2310.58,337.87 2314.08,341.37 2335.92,341.37 2339.42,337.87 4700.53,337.87 4880.53,517.87 5798.31,517.87 6020.43,740 U6.11@6020.43,1113.86
L1: D42.2 U6.10 | length 4279.1
  Bottom Layer w15: v2(2325,315) 4710,315 4890,495 5815,495 6046.02,726.02 U6.10@6046.02,1113.86
L2: D14.2 U6.9 | length 1228.4
  Bottom Layer w15: v2(5355,440) 5385,470 5425,470 5825,470 6071.61,716.61 U6.9@6071.61,1113.86
L3: D29.2 U6.8 | length 784.5
  Bottom Layer w15: v2(5830,440) 6097.2,707.2 U6.8@6097.2,1113.86
L4: D3.2 U6.7 | length 594.8
  Bottom Layer w15: U6.7@6122.8,1113.86 6122.8,727.2 v2(6270,580)
L5: D16.2 U6.6 | length 774.1
  Bottom Layer w15: U6.6@6148.39,1113.86 6148.39,746.61 6300,595 6300,445 v2(6270,415)
L6: D4.2 U6.5 | length 973.8
  Bottom Layer w15: U6.5@6173.98,1113.86 6173.98,756.02 6355,575 v2(6715,575)
L7: D34.2 U6.4 | length 1151
  Bottom Layer w15: U6.4@6199.57,1113.86 6199.57,765.43 6360,605 6725,605 6745,585 6745,445 v2(6715,415)
L8: D5.2 U6.25 | length 1548.1
  Bottom Layer w15: U6.25@6199.57,1346.14 6199.57,1454.17 6230.39,1485 6400,1485 7165,720 v2(7165,575)
L9: D17.2 U6.24 | length 1794.5
  Bottom Layer w15: U6.24@6173.98,1346.14 6173.98,1460.93 6220.92,1507.87 6409.47,1507.87 7187.87,729.47 ; v2(7160,415) 7191.37,446.37 7191.37,725.97
L10: D6.2 U6.23 | length 2011.2
  Bottom Layer w15: U6.23@6148.39,1346.14 6148.39,1467.69 6211.45,1530.75 6418.95,1530.75 7214.25,735.45 7214.25,733.71 7353.58,594.38 7355.32,594.38 7374.7,575 v2(7615,575)
L11: D35.2 U6.22 | length 2266.6
  Bottom Layer w15: U6.22@6122.8,1346.14 6122.8,1471.42 6125.51,1474.13 6125.51,1477.16 6203.35,1555 6425.3,1555 6426.68,1553.62 6428.42,1553.62 7237.12,744.92 7237.12,743.18 7363.05,617.25 7610.05,617.25 7641.37,585.92 7641.37,446.37 v2(7610,415)
L12: D18.2 U6.19 | length 2764.7
  Top Layer w15: v2(7620,690) 7944,690 7979.06,654.94 D18.2@7979.06,430
  Bottom Layer w15: U6.19@6046.02,1346.14 6046.02,1494.72 6179.16,1627.85 6191.89,1627.85 ; 6191.91,1627.87 6451.22,1627.87 7389.09,690 v2(7620,690)
L13: D36.2 U6.18 | length 6909.6
  Bottom Layer w15: U6.18@6020.43,1346.14 6020.43,1501.87 6170.56,1652 6459.44,1652 7387.44,724 7643.05,724 7859.17,507.87 8527.13,507.87 8780,255 11710,255 11815,360 v2(12090,360)
L14: D27.2 U6.20 | length 3130.2
  Bottom Layer w15: U6.20@6071.61,1346.14 6071.61,1487.96 6188.63,1604.98 6201.37,1604.98 ; 6201.39,1605 6440,1605 6445.63,1599.37 6447.37,1599.37 7282.87,763.87 7282.87,762.13 7382,663 7671.7,663 7849.7,485 8490,485 v2(8530,445)
L15: D27.1 R33.1 U6.21 | length 2943.7
  Top Layer w20: R33.1@8200,441.5 v2(8255,441.5) D27.1@8332.44,441.5
  Top Layer w23: D27.1@8332.44,441.5 D27.1@8340.94,450
  Bottom Layer w15: U6.21@6097.2,1346.14 6097.2,1481.2 ; 6101.7,1485.7 6195,1579 6433.65,1579 6436.16,1576.5 6437.9,1576.5 7260,754.4 7260,752.66 7372.53,640.13 7662.22,640.13 7842.35,460 8236.5,460 v2(8255,441.5)
L16: D19.2 U7.11 | length 2057.6
  Bottom Layer w15: U7.11@12130.43,2243.86 12130.43,1544.57 12133.15,1541.85 12133.15,1534.5 12550,1117.65 v2(12550,360)
L17: D12.2 U7.10 | length 2225.5
  Bottom Layer w15: U7.10@12156.02,2243.86 12156.02,1543.98 12660,1040 12660,715 v2(13005,370)
L18: D37.2 U7.9 | length 1785.6
  Bottom Layer w15: U7.9@12181.61,2243.86 12181.61,1558.39 12910,830 v2(12980,830)
L19: D20.2 U7.8 | length 2226.5
  Bottom Layer w15: U7.8@12207.2,2243.86 12207.2,1572.8 12355,1425 12710,1425 13305,830 v2(13455,830)
L20: D30.2 U7.7 | length 2417.5
  Bottom Layer w15: U7.7@12232.8,2243.86 12232.8,1587.2 12345,1475 13035,1475 v2(13680,830)
L21: D38.2 U7.6 | length 1912.1
  Bottom Layer w15: U7.6@12258.39,2243.86 12258.39,1601.61 12350,1510 13130,1510 13360,1280 v2(13395,1280)
L22: D13.2 U7.5 | length 2136
  Bottom Layer w15: U7.5@12283.98,2243.86 12283.98,1611.02 12360,1535 13395,1535 v2(13650,1280)
L23: D21.2 U7.4 | length 1824.7
  Bottom Layer w15: U7.4@12309.57,2243.86 12309.57,1620.43 12365,1565 13205,1565 v2(13405,1765)
L24: D39.2 U7.23 | length 1921.8
  Bottom Layer w15: U7.23@12258.39,2476.14 12258.39,2578.39 12315,2635 12545,2635 13280,1900 v2(13750,1900)
L25: D22.2 U7.22 | length 1638.6
  Bottom Layer w15: U7.22@12232.8,2476.14 12234.15,2477.5 12234.15,2586.5 12305.53,2657.87 12554.47,2657.87 12982.35,2230 v2(13555,2230)
L26: D41.2 U7.21 | length 1503.3
  Bottom Layer w15: U7.21@12207.2,2476.14 12207.2,2591.9 12296.05,2680.75 13530.75,2680.75 v2(13550,2700)
L27: D31.2 U7.20 | length 1682
  Bottom Layer w15: U7.20@12181.61,2476.14 12181.61,2598.66 12286.58,2703.62 13193.62,2703.62 v2(13550,3060)
L28: D40.2 U7.19 | length 4196.7
  Bottom Layer w15: v2(9270,5280) 9605,5280 12157.38,2727.62 12157.38,2477.5 U7.19@12156.02,2476.14
L29: D23.2 U7.18 | length 9406.6
  Top Layer w15: v2(4935,5275) v2(4935,5800)
  Bottom Layer w15: v2(4935,5800) 4990,5855 8550,5855 8807,5598 8807,5378 9080,5105 9730,5105 12131.79,2703.21 12131.79,2477.5 U7.18@12130.43,2476.14
NetC1_1: C1.1 R1.1 | length 98.5
  Bottom Layer w30: C1.1@6080,5593.62 6130.94,5593.62 R1.1@6164.57,5560
NetC1_2: C1.2 D1.1 D1.2 L1.2 Q2.5 TP1.1 | length 199.7
  Bottom Layer w20: L1.2@5966.65,5550 5966.65,5716.65 TP1.1@5990,5740
NetC2_1: C2.1 L2.1 Q1.5 Q1.6 Q1.7 Q1.8 Q1.9 TP4.1 U2.4 | length 208.5
  Bottom Layer w23: U2.4@4047.4,5555.87 4145.87,5555.87 4156.02,5545.71 L2.1@4156.02,5450
NetC11_2: C11.2 U2.1 | length 94.3
  Bottom Layer w23: C11.2@3880,5660 3884.13,5664.13 U2.1@3972.6,5664.13
NetC14_1: C14.1 R3.1 R6.2 | length 100
  Top Layer w10: R6.2@6080,4896.38 C14.1@6130,4896.38 R3.1@6180,4896.38
NetC19_1: C19.1 R13.1 | length 65.2
  Bottom Layer w10: C19.1@5980,4833.62 5973.62,4840 5973.62,4875 R13.1@5988.62,4890
NetC20_1: C20.1 C21.1 R14.2 R15.1 U3.13 U3.14 | length 504.5
  Bottom Layer w15: U3.13@4262.2,4717.21 U3.14@4262.2,4691.62 4322,4691.62 C21.1@4340,4673.62 4361.34,4694.96 C20.1@4510,4694.96 R14.2@4510,4782.91 4469.29,4823.62 R15.1@4400,4823.62
NetC22_1: C22.1 U3.3 | length 137.7
  Bottom Layer w9: C22.1@3901.5,4695 3904.88,4691.62 U3.3@4037.79,4691.62
NetC22_2: C22.2 L3.1 U3.1 U3.2 | length 61.5
  Bottom Layer w25: C22.2@3838.5,4695 3838.5,4651.5 3850,4640 3850,4638.27
NetC28_1: C28.1 U4.4 | length 116.5
  Top Layer w15: v2(7621.57,5253.43) 7658.15,5290 C28.1@7671.38,5290
  Bottom Layer w9: v2(7621.57,5253.43) 7641.17,5273.02 7663.43,5273.02 U4.4@7663.43,5274.57
NetC28_2: C28.2 L4.1 U4.12@7721.02,5310 | length 97.9
  Top Layer w15: C28.2@7718.62,5290 7760,5290 v2(7780,5310)
  Bottom Layer w13: L4.1@7892.83,5310 L4.1@7912.83,5290
NetC33_2: C33.2 U3.4 | length 230.8
  Bottom Layer w8: 3873.37,4726.63 3931.02,4726.63 3946.08,4726.63 3956.28,4716.42
  Bottom Layer w9: C33.2@3830,4770 3873.37,4726.63
  Bottom Layer w15: 3956.28,4716.42 4037.79,4716.42 U3.4@4037.79,4717.21
NetC41_1: C41.1 U3.11 | length 81.1
  Bottom Layer w15: U3.11@4262.2,4768.39 4332.01,4768.39 C41.1@4340,4776.38
NetC54_1: C54.1 R64.1 | length 100.9
  Bottom Layer w30: R64.1@7650.55,3720 7654.17,3716.38 C54.1@7750,3716.38
NetC54_2: C54.2 D51.2 L5.2 TP24.1 U8.18 | length 1128.5
  5V w15: TP24.1@7100,4970 7100,4825 v2(7675,4250)
  Bottom Layer w30: D51.2@7688.74,3900 7688.74,3829.76 7750,3768.5 C54.2@7750,3763.62 C54.2@7750,3755
NetC61_2: C61.2 R65.1 R66.2 U8.16 | length 377.2
  Top Layer w15: v2(7932,4079) 7941,4079 8017.2,4002.8 v2(8017.2,3972.8)
  Bottom Layer w15: C61.2@7897.5,3982.8 7897.5,4040.67 R65.1@7899.62,4042.8 7906,4036.42 R66.2@7956,4036.42 7956,4064 7941,4079 v2(7932,4079) ; v2(8017.2,3972.8) U8.16@8069.92,3972.8
NetC66_1: C66.1 U8.2 | length 132.4
  Bottom Layer w15: U8.2@8310.08,4049.57 8379.57,4049.57 8390,4060 C66.1@8438.19,4060
NetC67_2: C67.2 Q3.2 R71.1 TP30.1 U10.4 | length 785.9
  Top Layer w23: TP30.1@8660,746.6 TP30.1@8660,760 8890,530 v2(8890,522.6) Q3.2@8890,471.5 ; Q3.2@8884,477.5 Q3.2@8890,471.5 ; Q3.2@8891.5,470 Q3.2@8890,471.5
  Bottom Layer w23: v2(8890,522.6) U10.4@8924.57,522.6 8964.17,483 9103.2,483 R71.1@9158.7,538.5 C67.2@9228.7,538.5
NetC70_1: C70.1 R73.2 | length 66.8
  Bottom Layer w10: C70.1@10380,5224.5 R73.2@10380,5291.31
NetC70_2: C70.2 C71.1 R74.2 | length 130.6
  Bottom Layer w10: C71.1@10312.62,5242 R74.2@10312.62,5191 10342.12,5161.5 C70.2@10380,5161.5
NetC72_1: C72.1 R75.1 | length 60
  Bottom Layer w13: C72.1@10513.62,5340 R75.1@10513.62,5400
NetC73_1: C73.1 U9.2 | length 97.8
  Bottom Layer w13: U9.2@10363.66,5462.8 10451.3,5462.8 C73.1@10458.5,5470
NetC74_1: C74.1 R77.1 R78.2 U10.3 | length 363.1
  Top Layer w23: v2@9093,414 v2(9093,522.6)
  Bottom Layer w23: C74.1@8898.7,411.5 R77.1@9038.7,411.5 v2@9093,411.5 ; U10.3@9032.83,522.6 v2(9093,522.6)
  other v2: 9093,411
NetD3_1: D3.1 R24.1 | length 152.8
  Top Layer w20: R24.1@5940,548.5 5988.5,548.5 6020,580 6079.72,580
NetD4_1: D4.1 R25.1 | length 168.2
  Top Layer w20: R25.1@6390,528.5 6421.5,528.5 6473,580 D4.1@6536.85,580
NetD5_1: D5.1 R26.1 | length 164
  Top Layer w20: R26.1@6840,538.5 6869.5,538.5 6911,580 D5.1@6986.85,580
NetD6_1: D6.1 R27.1 | length 174
  Top Layer w20: R27.1@7280,538.5 7334.5,538.5 7376,580 D6.1@7436.85,580
NetD7_2: D7.2 J2.1 J3.2 | length 476.4
  Top Layer w25: J2.1@530,1990 529.06,1990.94 D7.2@529.06,2190 J3.2@805.09,2190
NetD10_1: D10.1 R34.1 | length 194.5
  Top Layer w20: R34.1@230,2628.5 412.44,2628.5 D10.1@420.94,2620
NetD11_1: D11.1 R36.1 | length 135.7
  Top Layer w20: R36.1@640,808.5 759.45,808.5 D11.1@770.94,820
NetD12_1: D12.1 R38.1 | length 161.6
  Top Layer w20: R38.1@12660,371.5 12819.45,371.5 D12.1@12820.94,370
NetD13_1: D13.1 R40.1 | length 141.6
  Top Layer w20: D13.1@13839.06,1280 13840.55,1278.5 R40.1@13980,1278.5
NetD14_1: D14.1 R42.1 | length 161.6
  Top Layer w20: R42.1@4980,441.5 5139.45,441.5 D14.1@5140.94,440
NetD15_1: D15.1 R44.1 | length 129.8
  Top Layer w20: R44.1@170,1668.5 269.45,1668.5 D15.1@290.94,1690
NetD16_1: D16.1 R46.1 | length 149.8
  Top Layer w20: R46.1@5940,441.5 6059.45,441.5 D16.1@6080.94,420
NetD17_1: D17.1 R48.1 | length 149.8
  Top Layer w20: R48.1@6830,441.5 6949.45,441.5 D17.1@6970.94,420
NetD18_1: D18.1 R50.1 | length 155.7
  Top Layer w20: R50.1@7710,441.5 7849.45,441.5 D18.1@7860.94,430
NetD19_1: D19.1 R52.1 | length 155.7
  Top Layer w20: R52.1@12210,371.5 12349.45,371.5 D19.1@12360.94,360
NetD20_1: D20.1 R54.1 | length 135.7
  Top Layer w20: R54.1@13130,831.5 13249.45,831.5 D20.1@13260.94,820
NetD21_1: D21.1 R56.1 | length 185.7
  Top Layer w20: R56.1@13020,1781.5 13189.45,1781.5 D21.1@13200.94,1770
NetD22_1: D22.1 R58.1 | length 169.8
  Top Layer w20: D22.1@13759.06,2230 13780.55,2208.5 R58.1@13920,2208.5
NetD23_1: D23.1 R60.1 | length 272.7
  Top Layer w25: R60.1@5098.5,5530 5098.5,5300.55 D23.1@5129.06,5270
NetD24_1: D24.1 R62.1 | length 155.7
  Top Layer w20: R62.1@1300,331.5 1439.45,331.5 D24.1@1450.94,320
NetD28_1: D28.1 R35.1 | length 159.8
  Top Layer w20: R35.1@650,1258.5 779.45,1258.5 D28.1@800.94,1280
NetD29_1: D29.1 R37.1 | length 151.6
  Top Layer w20: R37.1@5490,441.5 5639.45,441.5 D29.1@5640.94,440
NetD30_1: D30.1 R39.1 | length 189.8
  Top Layer w20: D30.1@13879.06,830 13900.55,808.5 R39.1@14060,808.5
NetD31_1: D31.1 R41.1 | length 181.6
  Top Layer w20: D31.1@13759.06,3060 13760.55,3058.5 R41.1@13940,3058.5
NetD32_1: D32.1 R43.1 | length 179.8
  Top Layer w20: R43.1@240,3038.5 389.45,3038.5 D32.1@410.94,3060
NetD33_1: D33.1 R45.1 | length 134
  Top Layer w20: R45.1@180,1228.5 269.45,1228.5 D33.1@300.94,1260
NetD34_1: D34.1 R47.1 | length 139.8
  Top Layer w20: R47.1@6390,441.5 6499.45,441.5 D34.1@6520.94,420
NetD35_1: D35.1 R49.1 | length 149.8
  Top Layer w20: R49.1@7280,441.5 7399.45,441.5 D35.1@7420.94,420
NetD36_1: D36.1 R51.1 | length 145.7
  Top Layer w20: R51.1@11760,371.5 11889.45,371.5 D36.1@11900.94,360
NetD37_1: D37.1 R53.1 | length 161.6
  Top Layer w20: R53.1@12610,831.5 12769.45,831.5 D37.1@12770.94,830
NetD38_1: D38.1 R55.1 | length 165.7
  Top Layer w20: R55.1@13030,1291.5 13179.45,1291.5 D38.1@13190.94,1280
NetD39_1: D39.1 R57.1 | length 225.6
  Top Layer w20: D39.1@13750,1690.94 13878.94,1690.94 13916.5,1728.5 R57.1@13960,1728.5
NetD40_1: D40.1 R59.1 | length 253.9
  Top Layer w20: R59.1@9071.5,5530 9071.5,5289.45 D40.1@9080.94,5280
NetD41_1: D41.1 R61.1 | length 195.7
  Top Layer w20: D41.1@13749.06,2700 13760.55,2688.5 R61.1@13940,2688.5
NetD42_1: D42.1 R63.1 | length 145.7
  Top Layer w20: R63.1@1990,331.5 2119.45,331.5 D42.1@2130.94,320
NetD43_2: D43.2 D44.1 | length 1333.9
  Top Layer w25: D44.1@5680,5173.15 5680,5275 5710,5305 6720,5305 6740,5285 D43.2@6740,5133.62
  other v2: 5719.37,5180 5720,5220
NetD44_2: D44.2 D45.1 | length 1342.3
  Top Layer w25: D45.1@4510.16,4680 v2(4625.08,4680) ; v2(4730,4680) 5146.38,5096.38 D44.2@5680,5096.38
  Bottom Layer w25: v2(4625.08,4680) v2(4730,4680)
NetD45_2: D45.2 D46.1 | length 2086.8
  Top Layer w25: D46.1@2513.15,4680 2568.17,4624.98 ; 2530,4685 2585,4630 2625,4630 2700,4555 4308.38,4555 D45.2@4433.38,4680
  other v2: 2520,4640.63 2545,4655 2545,4680 2545,4705 2515,4719.37
NetD46_2: D46.2 D47.1 | length 1030.3
  Top Layer w25: D47.1@1803.15,4020 1815,4031.85 1815,4243 2252,4680 D46.2@2436.38,4680
  other v2: 1805,3980.63 1850,3990 1850,4020 1850,4050 1805,4059.37 2369.45,4640.63 2430,4640.63 2369.45,4680 2369.45,4719.37 2430,4719.37
NetD47_2: D47.2 D48.1 | length 1276.2
  Top Layer w25: D48.1@1423.15,2920 1423.15,3803.15 1640,4020 D47.2@1726.38,4020
  other v2: 1430,2865 1470,2885 1470,2920 1470,2955 1430,2975 1659.45,3980.63 1725,3980 1659.45,4020 1659.45,4059.37 1725,4059.37
NetD48_2: D48.2 D49.1 | length 1256.9
  Top Layer w25: D48.2@1346.38,2920 1346.38,2205.62 1676.85,1875.15 D49.1@1676.85,1800
  other v2: 1670,1745 1630,1765 1630,1805 1630,1840 1670,1855 1270,2865 1346.38,2865 1270,2925 1270,2975 1345,2975
NetD49_2: D49.2 D50.1 | length 1223.7
  Top Layer w25: D49.2@1753.62,1800 2459,1800 2549,1710 2940,1710
  other v2: 2905,1685 2940,1685 2980,1685 2880,1715 3000,1715 1755,1745 1830,1745 1850,1805 1755,1855 1830,1855
NetD52_2: D52.2 D53.1 | length 1287.6
  Top Layer w25: D52.2@7460,5133.62 7530,5160 7565.63,5160 ; v2@7495,5165 7605,5165 7605,5060 7680,4985 7935,4985 8060,5110 8195,5110 8290,5205 8445,5205
  other v2: 7405,5120 7515,5120 7405,5175 7499.37,5175 8470,5195 8570,5195 7423.69,5210 8480,5220 8520,5220.71 8560,5220
NetD53_2: D53.2 D54.1 | length 3757.5
  Top Layer w25: D53.2@8520,5116.38 9391.38,5116.38 9855,5580 10450,5580 10610,5420 10755,5420 11485,4690 D54.1@11716.85,4690
  other v2: 11715,4640 11685,4655 11685,4690 11685,4725 11720,4740 8470,5040 8520,5040 8570,5040 8470,5115 8570,5115
NetD54_2: D54.2 D55.1 | length 989.8
  Top Layer w25: D54.2@11793.62,4690 11923,4690 12406.85,4206.15 D55.1@12406.85,4030
  other v2: 12390,3980 12365,4000 12365,4035 12365,4065 12390,4080 11795,4640 11880,4640 11880,4690 11795,4740 11880,4740
NetD55_2: D55.2 D56.1 | length 1239.7
  Top Layer w25: D55.2@12483.62,4030 12483.62,3901.38 12796.85,3588.15 D56.1@12796.85,2920
  other v2: 12780,2865 12750,2885 12750,2920 12750,2955 12780,2970 12485,3980 12575,3980 12575,4035 12480,4080 12575,4080
NetD56_2: D56.2 D57.1 | length 1246.9
  Top Layer w25: D57.1@12543.15,1810 12543.15,1933.15 12873.62,2263.62 D56.2@12873.62,2920
  other v2: 12545,1785 12580,1785 12580,1810 12580,1845 12543.15,1860 12870,2865 12965,2865 12965,2920 12870,2970 12965,2970
NetD57_2: D57.2 D58.1 | length 1208.4
  Top Layer w25: D58.1@11280,1863.15 11464.85,1863.15 11518,1810 D57.2@12466.38,1810
  other v2: 12465,1780.47 12395,1785 12395,1815 12395,1860 12465,1860 11225,1865 11335,1865 11250,1900 11280,1900 11310,1900
NetD58_2: D58.2 D59.1 | length 1034.7
  Top Layer w25: D59.1@10270,1726.85 10799.85,1726.85 10859.38,1786.38 D58.2@11280,1786.38
  other v2: 10235,1685 10270,1685 10300,1685 11225,1710 11280,1710 11335,1710 10230,1725 10310,1726.85 11335,1785 11225,1786.38
NetD60_2: D60.2 D61.1 | length 1224.9
  Top Layer w25: D61.1@8996.85,4030 8996.85,4131.85 9020,4155 9435,4155 9745,4465 9745,4512 9773.62,4540.62 D60.2@9773.62,4690
  other v2: 8995,3975 8960,4005 8960,4035 8960,4065 8996.85,4085 9773.62,4635 9850,4635 9850,4690 9775,4745 9850,4745
NetD61_2: D61.2 D62.1 | length 1299.2
  Top Layer w25: D62.1@8616.85,2920 8616.85,3139.85 9073.62,3596.62 D61.2@9073.62,4030
  other v2: 8615,2865 8575,2895 8575,2920 8575,2950 8616.85,2975 9075,3975 9150,3975 9150,4035 9075,4085 9150,4085
NetD62_2: D62.2 D63.1 | length 1292.1
  Top Layer w25: D62.2@8693.62,2920 8693.62,2661.38 9133.15,2221.85 D63.1@9133.15,1810
  other v2: 9135,1755 9175,1785 9175,1810 9175,1840 9133.15,1865 8693.62,2865 8770,2865 8770,2920 8695,2975 8770,2975
NetD63_2: D63.2 D64.1 | length 3696.2
  Bottom Layer w25: v2(5265,1800) 5280,1815 v2(8955,1815)
  other v2: 5225,1745 8980,1755 9055,1755 5265,1765 5265,1835 5225,1855 8980,1865 9055,1865
NetD64_2: D64.2 D65.1 | length 1226.7
  Top Layer w25: D65.1@3950,1726.85 4660.85,1726.85 4734,1800 D64.2@5146.38,1800
  other v2: 3915,1690 3950,1690 3985,1690 3895,1725 4005,1725 5070,1745 5150,1745 5070,1800 5070,1855 5150,1855
NetD65_2: D65.2 D66.1 | length 2044.4
  Top Layer w25: D65.2@3950,1803.62 3950,1939 4921,2910 D66.1@5456.85,2910
  other v2: 3895,1805 4005,1805 3895,1875 3950,1875 4005,1875 5460,2855 5415,2870 5415,2910 5415,2950 5455,2965
NetD66_2: D66.2 D67.1 | length 1299.2
  Top Layer w25: D67.1@5076.85,4020 5076.85,3593.15 5533.62,3136.38 D66.2@5533.62,2910
  other v2: 5535,2855 5605,2855 5605,2910 5535,2965 5605,2965 5076.85,3965 5030,3985 5030,4020 5030,4055 5075,4075
NetD68_1: D68.1 J5.19 | length 121.2
  Top Layer w15: J5.19@6300,2250 6346.34,2203.66 D68.1@6402,2203.66
NetQ1_4: Q1.4 U2.5 | length 112.7
  Bottom Layer w15: U2.5@4010,5555.87 4010,5516 4011.8,5514.2 4045.95,5514.2 4048.39,5511.76 Q1.4@4048.39,5479.06
NetQ2_1: Q2.1 Q2.2 Q2.3 R3.2 R4.2 | length 372.1
  Top Layer w15: 6125,5245 6170,5200 6170,4995 6180,4985 R3.2@6180,4943.62
  Bottom Layer w15: v2(6115,5255) 6115,5207.2 R4.2@6115.12,5207.09
NetQ2_4: Q2.4 R2.2 | length 65.8
  Bottom Layer w15: R2.2@6015.12,5223.62 6016.73,5225.24 Q2.4@6016.73,5288.78
NetR2_1: R2.1 U1.9 | length 141
  Bottom Layer w10: U1.9@5941.85,5078.39 5963.39,5078.39 6015.12,5130.12 R2.1@6015.12,5176.38
NetR5_2: R5.2 U1.3 | length 84.9
  Bottom Layer w10: R5.2@5720,5036.38 5736.42,5052.8 U1.3@5798.15,5052.8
